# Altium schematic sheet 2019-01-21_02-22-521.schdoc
size 386 x 140 mm; SheetNumber: 1; SheetTotal: 1
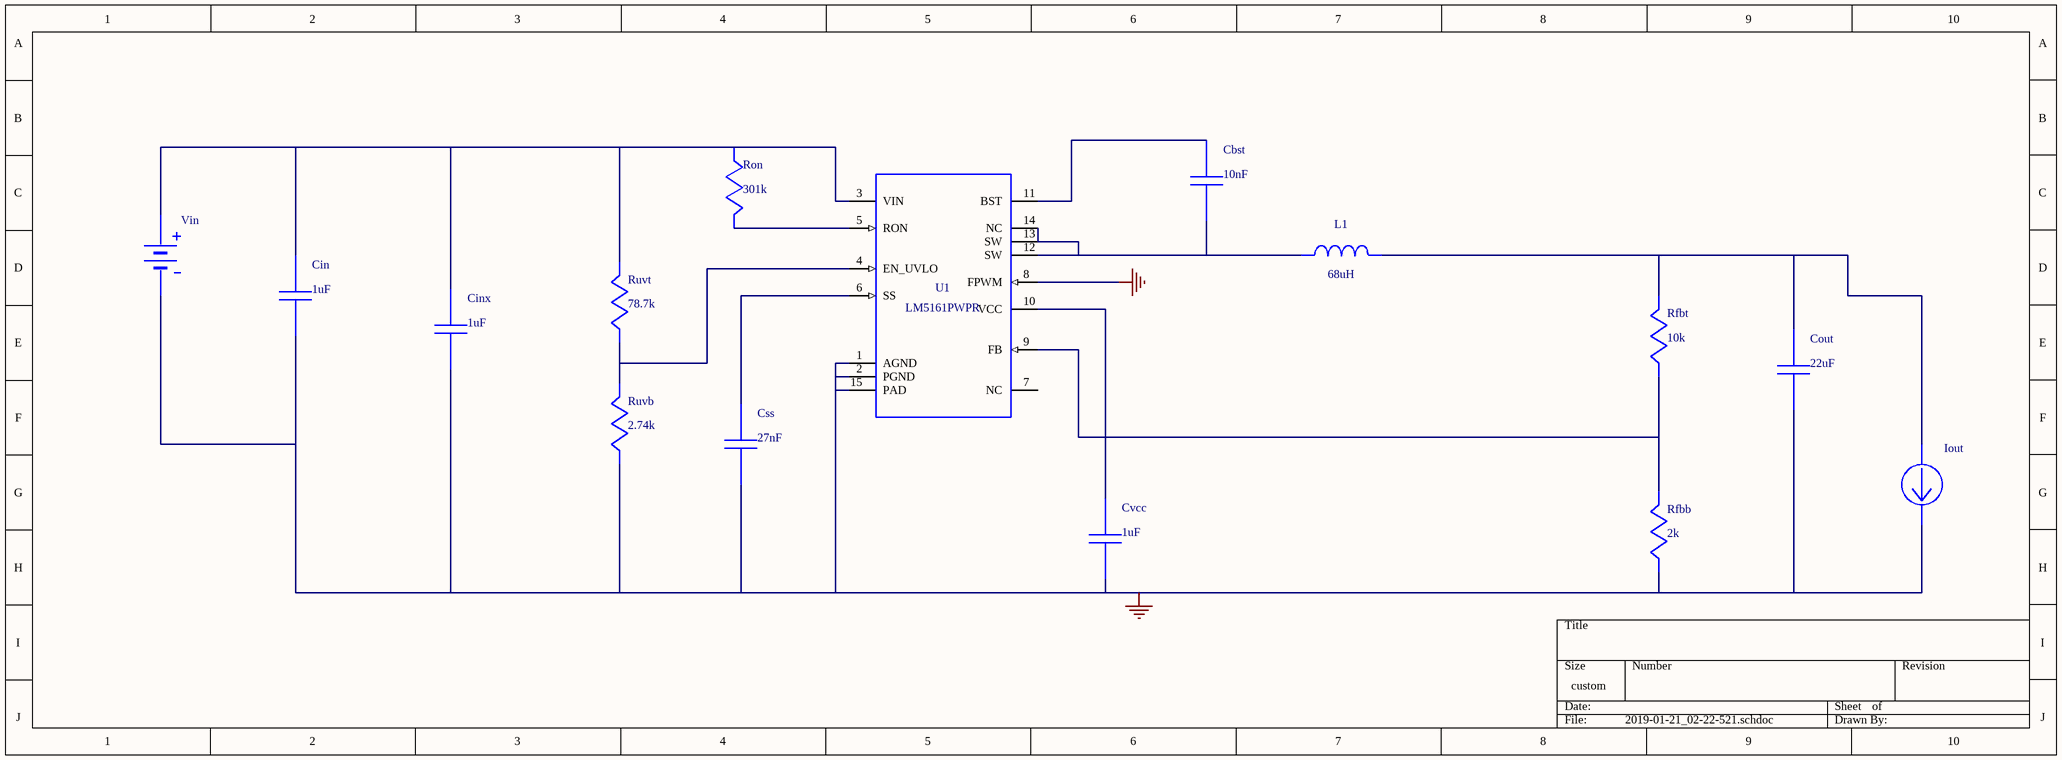
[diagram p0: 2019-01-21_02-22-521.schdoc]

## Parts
Cbst  value 10nF  (hidden comment: GRM155R71C103KA01D)
Cin  value 1uF  (hidden comment: GRM55DR72E105KW01L)
Cinx  value 1uF  (hidden comment: GRM55DR72E105KW01L)
Cout  value 22uF  (hidden comment: C2012X6S1C226M125AC)
Css  value 27nF  (hidden comment: GRM155R71C273KA01D)
Cvcc  value 1uF  (hidden comment: C0805C105K4RACTU)
Iout  WB_CURRENT_LOAD  (value not drawn)
L1  value 68uH  (hidden comment: MSS1038-683MLB)
Rfbb  value 2k  (hidden comment: CRCW04022K00FKED)
Rfbt  value 10k  (hidden comment: RMCF0402FT10K0)
Ron  value 301k  (hidden comment: ERJ-6ENF3013V)
Ruvb  value 2.74k  (hidden comment: CRCW04022K74FKED)
Ruvt  value 78.7k  (hidden comment: CRCW040278K7FKED)
U1  LM5161PWPR
Vin  WB_BATTERY  (value not drawn)

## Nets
0: Cin.2 Cinx.2 Cout.2 Css.2 Cvcc.1 Iout.2(-) Rfbb.2 Ruvb.2 U1.1(AGND) U1.2(PGND) U1.8(FPWM) U1.15(PAD) Vin.2(-)
NetCbst_1: Cbst.1 U1.11(BST)
NetCbst_2: Cbst.2 L1.1 U1.12(SW) U1.13(SW) U1.14(NC)
NetCin_1: Cin.1 Cinx.1 Ron.2 Ruvt.1 U1.3(VIN) Vin.1(+)
NetCout_1: Cout.1 Iout.1(+) L1.2 Rfbt.1
NetCss_1: Css.1 U1.6(SS)
NetCvcc_2: Cvcc.2 U1.10(VCC)
NetRfbb_1: Rfbb.1 Rfbt.2 U1.9(FB)
NetRon_1: Ron.1 U1.5(RON)
NetRuvb_1: Ruvb.1 Ruvt.2 U1.4(EN_UVLO)

Not connected (* = marked no-connect by the designer): U1 7(NC)

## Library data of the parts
Cbst = GRM155R71C103KA01D: GRM155R71C103KA0; Manufacturer Name: MuRata
Cin Cinx = GRM55DR72E105KW01L: GRM55DR72E105KW0; Manufacturer Name: MuRata
Cout = C2012X6S1C226M125AC: C2012X6S1C226M12; Manufacturer Name: TDK
Css = GRM155R71C273KA01D: GRM155R71C273KA0; Manufacturer Name: MuRata
Cvcc = C0805C105K4RACTU: Manufacturer Name: Kemet
L1 = MSS1038-683MLB: Manufacturer Name: Coilcraft
Rfbb = CRCW04022K00FKED: Manufacturer Name: Vishay-Dale
Rfbt = RMCF0402FT10K0: Manufacturer Name: Stackpole Electronics Inc
Ron = ERJ-6ENF3013V: Manufacturer Name: Panasonic
Ruvb = CRCW04022K74FKED: Manufacturer Name: Vishay-Dale
Ruvt = CRCW040278K7FKED: Manufacturer Name: Vishay-Dale
U1 = LM5161PWPR: Manufacturer Name: Texas Instruments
